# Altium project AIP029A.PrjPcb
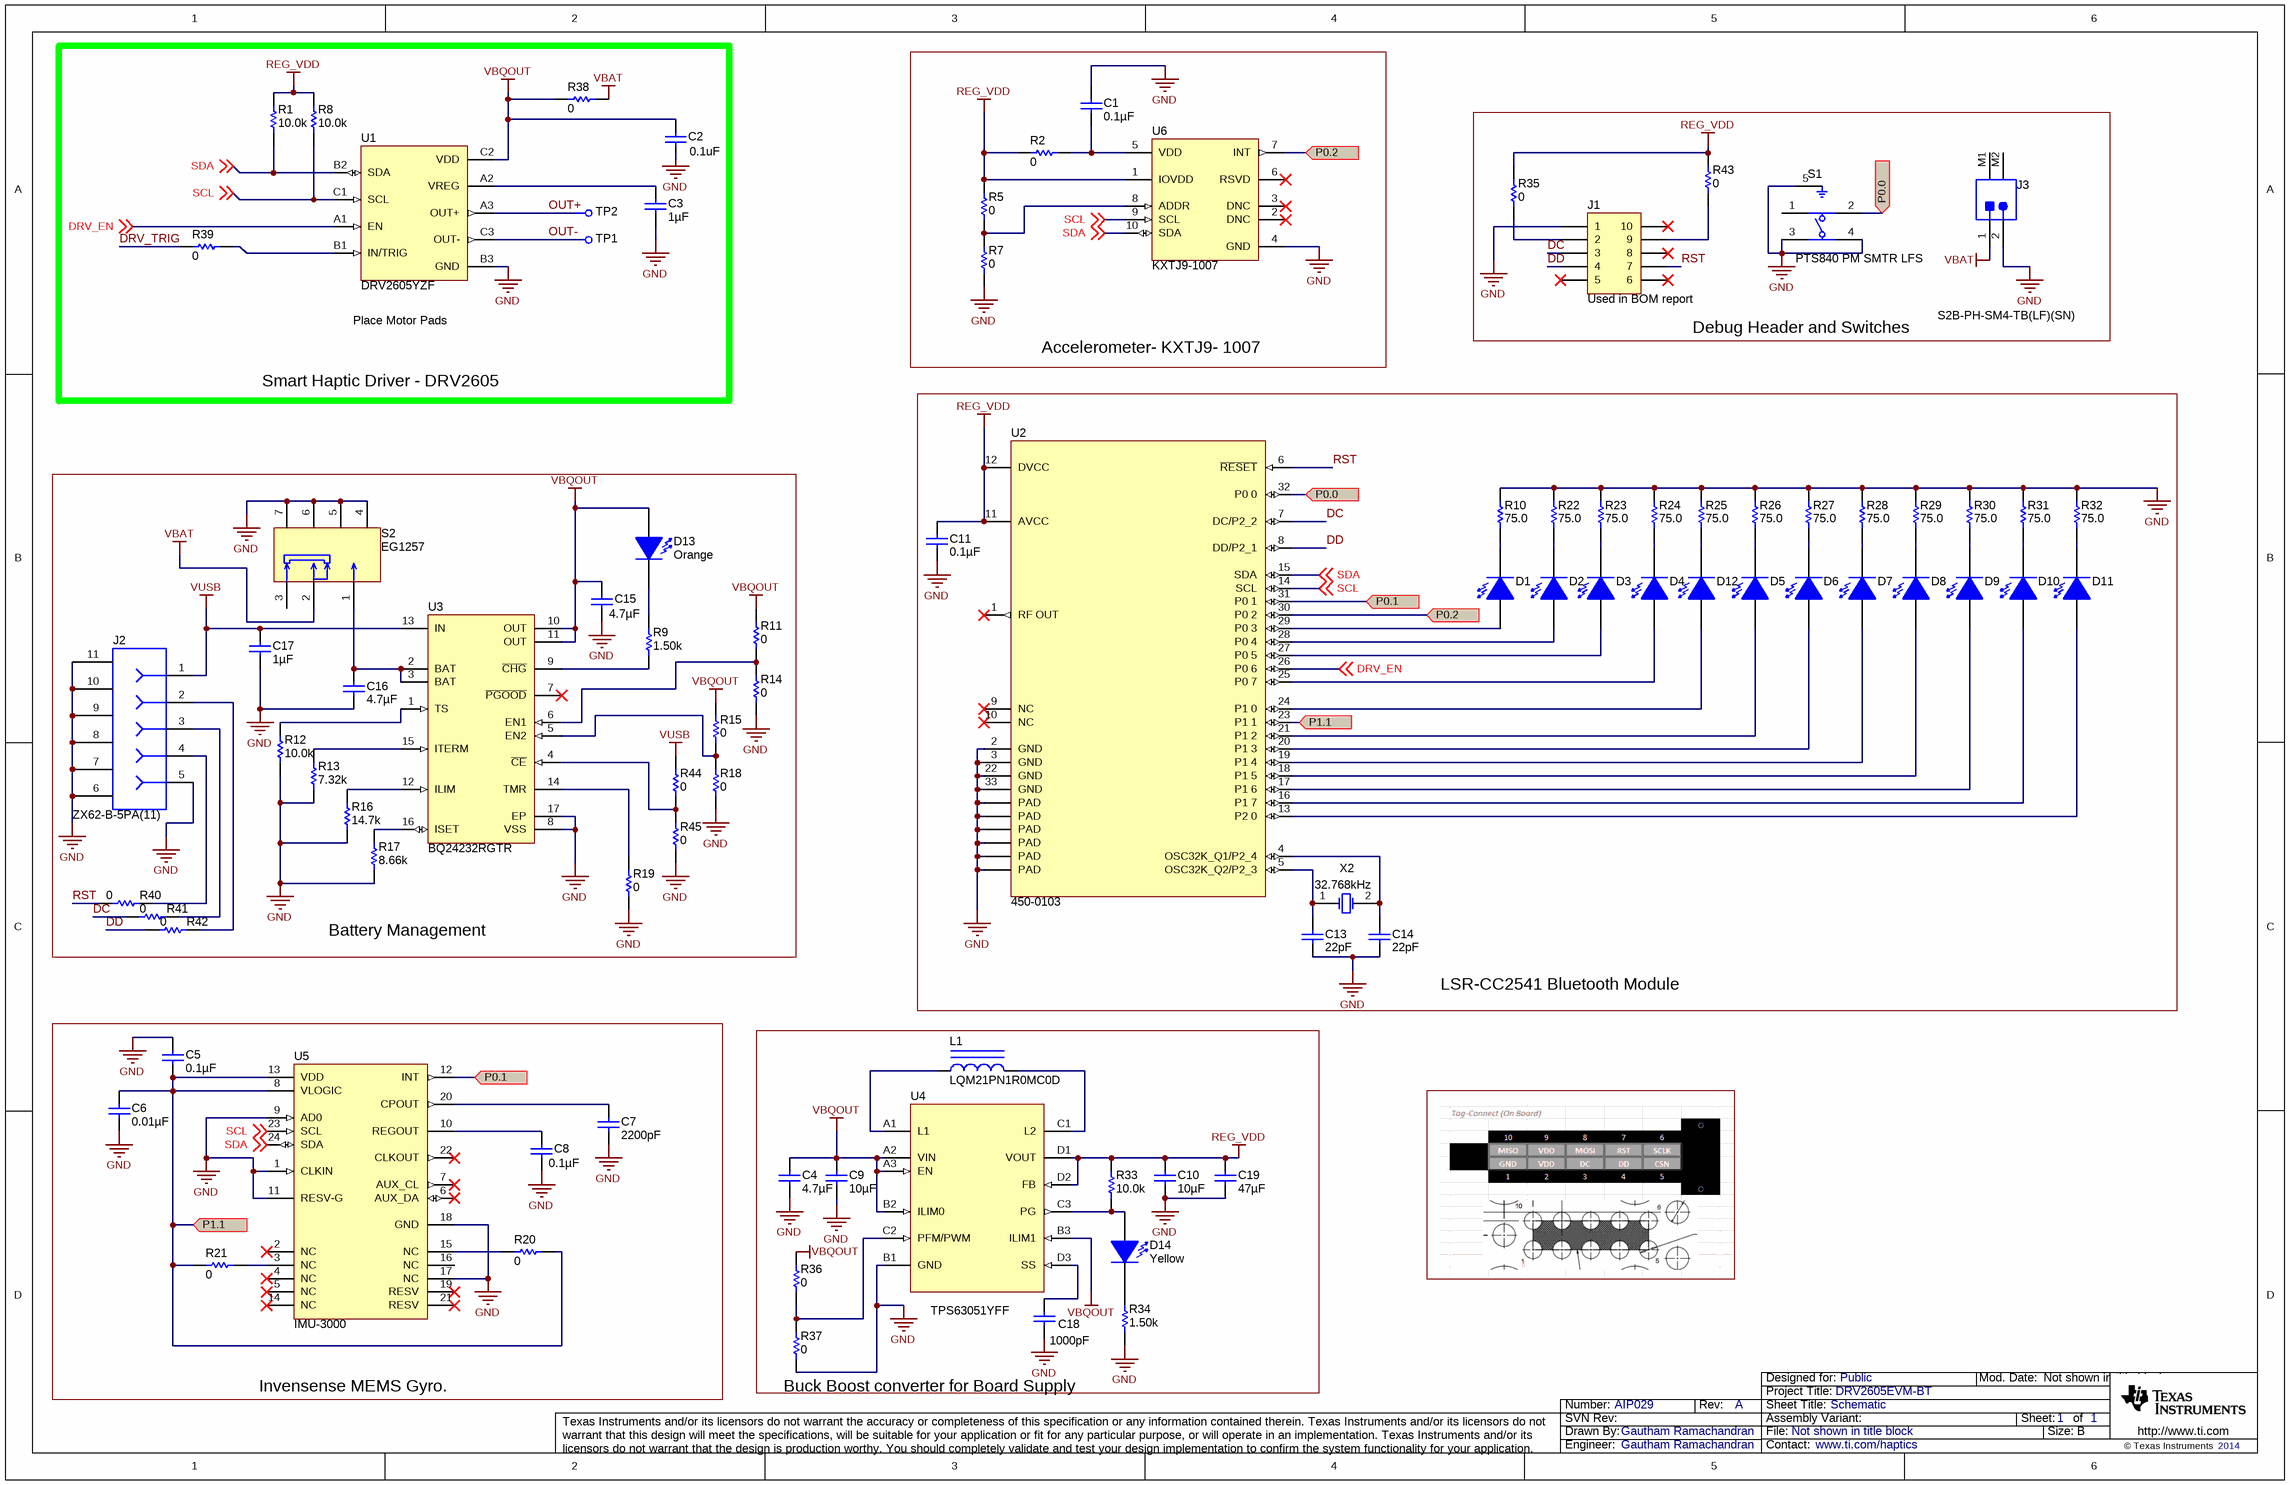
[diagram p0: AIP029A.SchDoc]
CopyrightYear: 2014; PCB_Layout: Gautham Ramachandran; PCB_Rev: A; PRJ_Customer: Public; PRJ_Engineer: Gautham Ramachandran; PRJ_Number: AIP029; PRJ_Title: DRV2605EVM-BT; SCH_Rev: A; TechSupport: www.ti.com/haptics
2 sheets, 96 parts. Net scope: flat (ports and power ports of the same name join across sheets).
Board file: AIP029A.PcbDoc
Sheets:
  AIP029A.SchDoc
  AIP029A_Hardware.SchDoc

## Sheet AIP029A.SchDoc: Schematic
size 431 x 279 mm; Date: Not shown in title block; ApprovedBy: Brian Burk; CheckedBy: Not shown in title block; Author: Gautham Ramachandran; CompanyName: Texas Instruments; DrawnBy: Gautham Ramachandran; Engineer: Brian Burk; Organization: Not shown in title block; Address1: Not shown in title block; Address2: Not shown in title block; Address3: Not shown in title block; DocumentNumber: 1; Revision: Use project parameter SCH_Rev; SheetNumber: 1; SheetTotal: 1; PageSetup: Record=PageOptions|CenterHorizontal=True|CenterVertical=True|PrintScale=0.62|XCorrection=1.00|YCorrection=1.00|PrintKind=0|BorderSize=5000000|LeftOffset=0|BottomOffset=0|Orientation=2|PaperLength=1000|PaperWidth=1000|Scale=100|PaperSource=15|PrintQuality=600|MediaType=1|DitherType=10|PaperKind=Letter|PrintScaleMode=1

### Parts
C1  ValueDisplayed: 0.1µF  [0402S]  (hidden comment: GRM155R71C104KA88D)
C2  value 0.1uF  [0402S]  (hidden comment: GRM155R71C104KA88D)
C3  ValueDisplayed: 1µF  [0402S]  (hidden comment: GRM155R61A105KE15D)
C4  ValueDisplayed: 4.7µF  [0402S]  (hidden comment: C1005X5R0J475M050BC)
C5  ValueDisplayed: 0.1µF  [0402S]  (hidden comment: GRM155R71A104KA01D)
C6  ValueDisplayed: 0.01µF  [0402S]  (hidden comment: GRM155R71E103KA01D)
C7  ValueDisplayed: 2200pF  [0402S]  (hidden comment: GRM155R71H222KA01D)
C8  ValueDisplayed: 0.1µF  [0402S]  (hidden comment: GRM155R71A104KA01D)
C9  ValueDisplayed: 10µF  [0603L]  (hidden comment: C1608X5R1A106M)
C10  ValueDisplayed: 10µF  [0603L]  (hidden comment: C1608X5R1A106M)
C11  ValueDisplayed: 0.1µF  [0402S]  (hidden comment: C1005X7R1H104K)
C13  ValueDisplayed: 22pF  [0402S]  (hidden comment: GRM1555C1H220JA01D)
C14  ValueDisplayed: 22pF  [0402S]  (hidden comment: GRM1555C1H220JA01D)
C15  ValueDisplayed: 4.7µF  [0402S]  (hidden comment: GRM155R61A475M)
C16  ValueDisplayed: 4.7µF  [0402S]  (hidden comment: GRM155R61A475M)
C17  ValueDisplayed: 1µF  [0402S]  (hidden comment: GRM155R61A105KE15D)
C18  ValueDisplayed: 1000pF  [0402S]  (hidden comment: C1005C0G1E102J)
C19  ValueDisplayed: 47µF  [0603]  (hidden comment: GRM188R60J476M)
D1  SML312WBCW1  [LED_SML]  (value not drawn)
D2  SML312WBCW1  [LED_SML]  (value not drawn)
D3  SML312WBCW1  [LED_SML]  (value not drawn)
D4  SML312WBCW1  [LED_SML]  (value not drawn)
D5  SML312WBCW1  [LED_SML]  (value not drawn)
D6  SML312WBCW1  [LED_SML]  (value not drawn)
D7  SML312WBCW1  [LED_SML]  (value not drawn)
D8  SML312WBCW1  [LED_SML]  (value not drawn)
D9  SML312WBCW1  [LED_SML]  (value not drawn)
D10  SML312WBCW1  [LED_SML]  (value not drawn)
D11  SML312WBCW1  [LED_SML]  (value not drawn)
D12  SML312WBCW1  [LED_SML]  (value not drawn)
D13  value Orange  [LED_SMLP12_ORANGE]  (hidden comment: SML-P12DTT86)
D14  value Yellow  [LED_SMLP12_Yellow]  (hidden comment: SML-P12YTT86)
J1  Used in BOM report  [PCBComponent_1]
J2  ZX62-B-5PA(11)  [CONN_USB_micro_ZX62-B-5PA]
J3  S2B-PH-SM4-TB(LF)(SN)  [JST_S2B-PH-SM4-TB]
L1  LQM21PN1R0MC0D  [0805]
R1  value 10.0k  [0402S]  (hidden comment: CRCW040210K0FKED)
R2  value 0  [0402S]  (hidden comment: CRCW04020000Z0ED)
R5  value 0  [0402S]  (hidden comment: CRCW04020000Z0ED)
R7  value 0  [0402S]  (hidden comment: CRCW04020000Z0ED)
R8  value 10.0k  [0402S]  (hidden comment: CRCW040210K0FKED)
R9  value 1.50k  [0402S]  (hidden comment: CRCW04021K50FKED)
R10  value 75.0  [0402S]  (hidden comment: CRCW040275R0FKED)
R11  value 0  [0402S]  (hidden comment: CRCW04020000Z0ED)
R12  value 10.0k  [0402S]  (hidden comment: CRCW040210K0FKED)
R13  value 7.32k  [0402S]  (hidden comment: CRCW04027K32FKED)
R14  value 0  [0402S]  (hidden comment: CRCW04020000Z0ED)
R15  value 0  [0402S]  (hidden comment: CRCW04020000Z0ED)
R16  value 14.7k  [0402S]  (hidden comment: CRCW040214K7FKED)
R17  value 8.66k  [0402S]  (hidden comment: CRCW04028K66FKED)
R18  value 0  [0402S]  (hidden comment: CRCW04020000Z0ED)
R19  value 0  [0402S]  (hidden comment: CRCW04020000Z0ED)
R20  value 0  [0402S]  (hidden comment: CRCW04020000Z0ED)
R21  value 0  [0402S]  (hidden comment: CRCW04020000Z0ED)
R22  value 75.0  [0402S]  (hidden comment: CRCW040275R0FKED)
R23  value 75.0  [0402S]  (hidden comment: CRCW040275R0FKED)
R24  value 75.0  [0402S]  (hidden comment: CRCW040275R0FKED)
R25  value 75.0  [0402S]  (hidden comment: CRCW040275R0FKED)
R26  value 75.0  [0402S]  (hidden comment: CRCW040275R0FKED)
R27  value 75.0  [0402S]  (hidden comment: CRCW040275R0FKED)
R28  value 75.0  [0402S]  (hidden comment: CRCW040275R0FKED)
R29  value 75.0  [0402S]  (hidden comment: CRCW040275R0FKED)
R30  value 75.0  [0402S]  (hidden comment: CRCW040275R0FKED)
R31  value 75.0  [0402S]  (hidden comment: CRCW040275R0FKED)
R32  value 75.0  [0402S]  (hidden comment: CRCW040275R0FKED)
R33  value 10.0k  [0402S]  (hidden comment: CRCW040210K0FKED)
R34  value 1.50k  [0402S]  (hidden comment: CRCW04021K50FKED)
R35  value 0  [0402S]  (hidden comment: CRCW04020000Z0ED)
R36  value 0  [0402S]  (hidden comment: CRCW04020000Z0ED)
R37  value 0  [0402S]  (hidden comment: CRCW04020000Z0ED)
R38  value 0  [0402S]  (hidden comment: CRCW04020000Z0ED)
R39  value 0  [0402S]  (hidden comment: CRCW04020000Z0ED)
R40  value 0  [0402S]  (hidden comment: CRCW04020000Z0ED)
R41  value 0  [0402S]  (hidden comment: CRCW04020000Z0ED)
R42  value 0  [0402S]  (hidden comment: CRCW04020000Z0ED)
R43  value 0  [0402S]  (hidden comment: CRCW04020000Z0ED)
R44  value 0  [0402L]  (hidden comment: CRCW04020000Z0ED)
R45  value 0  [0402S]  (hidden comment: CRCW04020000Z0ED)
S1  PTS840 PM SMTR LFS  [SW_PTS840 P]
S2  EG1257  [SW_EG1257]
TP1  (no value)  [DUMMY-PAD]
TP2  (no value)  [DUMMY-PAD]
U1  DRV2605YZF  [YZF0009ADAD]
U2  450-0103  [TiWi-uB1]
U3  BQ24232RGTR  [RGT0016C]
U4  TPS63051YFF  [YFF0012AFAF]
U5  IMU-3000  [QFN50P400X400X95-24N]
U6  KXTJ9-1007  [LGA3X3MM_0.65]
X2  Frequency: 32.768kHz  [XTAL_NX3215SA]  (hidden comment: NX3215SA-32.768K-STD-MUS-2)

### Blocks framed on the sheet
Smart Haptic Driver - DRV2605: C2 C3 R1 R8 R38 R39 TP1 TP2 U1
Accelerometer- KXTJ9- 1007: C1 R2 R5 R7 U6
Debug Header and Switches: J1 J3 R35 R43 S1
LSR-CC2541 Bluetooth Module: C11 C13 C14 D1-D12 R10 R22-R32 U2 X2
Battery Management: C15-C17 D13 J2 R9 R11-R19 R40-R42 R44 R45 S2 U3
Invensense MEMS Gyro.: C5-C8 R20 R21 U5
Buck Boost converter for Board Supply: C4 C9 C10 C18 C19 D14 L1 R33 R34 R36 R37 U4

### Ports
P0.0, P0.1, P0.2, P1.1

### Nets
GND: C1.1 C2.2 C3.2 C4.2 C5.1 C6.2 C7.2 C8.2 C9.2 C10.2 C11.1 C13.1 C14.1 C15.2 C16.2 C17.2 C18.2 C19.2 J1.1 J2.5 J2.6 J2.7 J2.8 J2.9 J2.10 J2.11 J3.2 R7.1 R10.1 R12.1 R13.1 R14.1 R16.1 R17.1 R18.1 R19.1 R22.1 R23.1 R24.1 R25.1 R26.1 R27.1 R28.1 R29.1 R30.1 R31.1 R32.1 R34.1 R37.1 R45.1 S1.3 S1.4 S1.5 S2.4 S2.5 S2.6 S2.7 U1.B3(GND) U2.2(GND) U2.3(GND) U2.22(GND) U2.33(GND) U2.34(PAD) U2.35(PAD) U2.36(PAD) U2.37(PAD) U2.38(PAD) U2.39(PAD) U3.8(VSS) U3.17(EP) U4.B1(GND) U5.1(CLKIN) U5.9(AD0) U5.11(RESV-G) U5.17(NC) U5.18(GND) U6.4(GND)
REG_VDD: C10.1 C11.2 C19.1 R1.2 R2.2 R5.2 R8.2 R33.2 R35.2 R43.2 U2.11(AVCC) U2.12(DVCC) U4.D1(VOUT) U4.D2(FB) U6.1(IOVDD)
VBAT: J3.1 R38.1 S2.2
VBQOUT: C2.1 C4.1 C9.1 C15.1 D13.1(A) R11.2 R15.2 R36.2 R38.2 U1.C2(VDD) U3.10(OUT) U3.11(OUT) U4.A2(VIN) U4.A3(EN) U4.B2(ILIM0) U4.B3(ILIM1)
VUSB: C17.1 J2.1 R44.2 U3.13(IN)
DC: J1.3 R41.2 U2.7(DC/P2_2)
DD: J1.4 R42.2 U2.8(DD/P2_1)
DRV_EN: U1.A1(EN) U2.26(P0_6) ; off-sheet DRV_EN
DRV_TRIG: R39.2
OUT+: U1.A3(OUT+)
OUT-: U1.C3(OUT-)
P0.0: S1.2 U2.32(P0_0) ; port P0.0
P0.1: U2.31(P0_1) U5.12(INT) ; port P0.1
P0.2: U2.30(P0_2) U6.7(INT) ; port P0.2
P1.1: C5.2 C6.1 R20.1 R21.2 U2.23(P1_1) U5.8(VLOGIC) U5.13(VDD) ; port P1.1
RST: J1.7 R40.2 U2.6(~{RESET})
SCL: R8.1 U1.C1(SCL) U2.14(SCL) U5.23(SCL) U6.9(SCL) ; off-sheet SCL
SDA: R1.1 U1.B2(SDA) U2.15(SDA) U5.24(SDA) U6.10(SDA) ; off-sheet SDA
NetC1_2: C1.2 R2.1 U6.5(VDD)
NetC3_1: C3.1 U1.A2(VREG)
NetC7_1: C7.1 U5.20(CPOUT)
NetC8_1: C8.1 U5.10(REGOUT)
NetC13_2: C13.2 U2.5(OSC32K_Q2/P2_3) X2.1(OSC1)
NetC14_2: C14.2 U2.4(OSC32K_Q1/P2_4) X2.2(OSC2)
NetC16_1: C16.1 S2.1 U3.2(BAT) U3.3(BAT)
NetC18_1: C18.1 U4.D3(SS)
NetD1_1: D1.1(A) U2.29(P0_3)
NetD1_2: D1.2(K) R10.2
NetD2_1: D2.1(A) U2.28(P0_4)
NetD2_2: D2.2(K) R22.2
NetD3_1: D3.1(A) U2.27(P0_5)
NetD3_2: D3.2(K) R23.2
NetD4_1: D4.1(A) U2.25(P0_7)
NetD4_2: D4.2(K) R24.2
NetD5_1: D5.1(A) U2.21(P1_2)
NetD5_2: D5.2(K) R26.2
NetD6_1: D6.1(A) U2.20(P1_3)
NetD6_2: D6.2(K) R27.2
NetD7_1: D7.1(A) U2.19(P1_4)
NetD7_2: D7.2(K) R28.2
NetD8_1: D8.1(A) U2.18(P1_5)
NetD8_2: D8.2(K) R29.2
NetD9_1: D9.1(A) U2.17(P1_6)
NetD9_2: D9.2(K) R30.2
NetD10_1: D10.1(A) U2.16(P1_7)
NetD10_2: D10.2(K) R31.2
NetD11_1: D11.1(A) U2.13(P2_0)
NetD11_2: D11.2(K) R32.2
NetD12_1: D12.1(A) U2.24(P1_0)
NetD12_2: D12.2(K) R25.2
NetD13_2: D13.2(K) R9.2
NetD14_1: D14.1(A) R33.1 U4.C3(PG)
NetD14_2: D14.2(K) R34.2
NetJ1_2: J1.2 R35.1
NetJ1_9: J1.9 R43.1
NetJ2_2: J2.2 R42.1
NetJ2_3: J2.3 R41.1
NetJ2_4: J2.4 R40.1
NetL1_1: L1.1 U4.A1(L1)
NetL1_2: L1.2 U4.C1(L2)
NetR5_1: R5.1 R7.2 U6.8(ADDR)
NetR9_1: R9.1 U3.9(~{CHG})
NetR11_1: R11.1 R14.2 U3.6(EN1)
NetR12_2: R12.2 U3.1(TS)
NetR13_2: R13.2 U3.15(ITERM)
NetR15_1: R15.1 R18.2 U3.5(EN2)
NetR16_2: R16.2 U3.12(ILIM)
NetR17_2: R17.2 U3.16(ISET)
NetR19_2: R19.2 U3.14(TMR)
NetR20_2: R20.2 U5.15(NC)
NetR21_1: R21.1 U5.3(NC)
NetR36_1: R36.1 R37.2 U4.C2(PFM/PWM)
NetR39_1: R39.1 U1.B1(IN/TRIG)
NetR44_1: R44.1 R45.2 U3.4(~{CE})

Not connected (* = marked no-connect by the designer): J1 5* 6* 8* 10*; J3 M1 M2; S1 1; S2 3; U2 1(RF_OUT)* 9(NC)* 10(NC)*; U3 7(~{PGOOD})*; U5 2(NC)* 4(NC)* 5(NC)* 6(AUX_DA)* 7(AUX_CL)* 14(NC)* 16(NC) 19(RESV)* 21(RESV)* 22(CLKOUT)*; U6 2(DNC)* 3(DNC)* 6(RSVD)*

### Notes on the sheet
- (near U1) Place Motor Pads

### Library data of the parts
C1 C2 = GRM155R71C104KA88D: CAP, CERM, 0.1uF, 16V, +/-10%, X7R, 0402; Manufacturer: MuRata; Polarized: N; CompType: Capacitor; U/M: EA; Cap_F: 0.0000001; Tolerance_%: 10; Value1: Unknown; VDC_V: 16; TaMin_C: -55; TaMax_C: 125; Cap_Case: 0402
C3 C17 = GRM155R61A105KE15D: CAP, CERM, 1uF, 10V, +/-10%, X5R, 0402; Manufacturer: MuRata; Polarized: N; CompType: Capacitor; U/M: EA; Cap_F: 0.000001; Tolerance_%: 10; Value1: Unknown; TaMin_C: -55; TaMax_C: 85; Cap_Case: 0402
C4 = C1005X5R0J475M050BC: CAP, CERM, 4.7uF, 6.3V, +/-20%, X5R, 0402; Manufacturer: TDK; Polarized: N; CompType: Capacitor; U/M: EA; Cap_F: 0.0000047; Tolerance_%: 20; Value1: Unknown; VDC_V: 6.3; TaMin_C: -55; TaMax_C: 85; Cap_Case: 0402
C5 C8 = GRM155R71A104KA01D: CAP, CERM, 0.1uF, 10V, +/-10%, X7R, 0402; Manufacturer: MuRata; Polarized: N; CompType: Capacitor; U/M: EA; Cap_F: 0.0000001; Tolerance_%: 10; Value1: Unknown; TaMin_C: -55; TaMax_C: 125; Cap_Case: 0402
C6 = GRM155R71E103KA01D: CAP, CERM, 0.01uF, 25V, +/-10%, X7R, 0402; Manufacturer: MuRata; Polarized: N; CompType: Capacitor; U/M: EA; Cap_F: 0.00000001; Tolerance_%: 10; Value1: Unknown; VDC_V: 25; TaMin_C: -55; TaMax_C: 125; Cap_Case: 0402
C7 = GRM155R71H222KA01D: CAP, CERM, 2200pF, 50V, +/-10%, X7R, 0402; Manufacturer: MuRata; Polarized: N; CompType: Capacitor; U/M: EA; Cap_F: 0.0000000022; Tolerance_%: 10; Value1: Unknown; VDC_V: 50; TaMin_C: -55; TaMax_C: 125; Cap_Case: 0402
C9 C10 = C1608X5R1A106M: CAP, CERM, 10uF, 10V, +/-20%, X5R, 0603; Manufacturer: TDK; Polarized: N; CompType: Capacitor; U/M: EA; Cap_F: 0.00001; Tolerance_%: 20; ESR_Ohm: 0.0078; Value1: 0.0078 ohm; VDC_V: 10; IRMS_A: 1.85; TaMin_C: -55; TaMax_C: 85; Cap_Case: 0603
C11 = C1005X7R1H104K: CAP, CERM, 0.1uF, 50V, +/-10%, C0G/NP0, 0402; Manufacturer: TDK; Polarized: N; CompType: Capacitor; U/M: EA; Cap_F: 0.0000001; Tolerance_%: 10; Value1: Unknown; VDC_V: 50; TaMin_C: -55; TaMax_C: 125; Cap_Case: 0402
C13 C14 = GRM1555C1H220JA01D: CAP, CERM, 22pF, 50V, +/-5%, C0G/NP0, 0402; Manufacturer: MuRata; Polarized: N; CompType: Capacitor; U/M: EA; Cap_F: 0.000000000022; Tolerance_%: 5; Value1: Unknown; VDC_V: 50; TaMin_C: -55; TaMax_C: 125; Cap_Case: 0402
C15 C16 = GRM155R61A475M: CAP, CERM, 4.7uF, 10V, +/-20%, X5R, 0402; Manufacturer: MuRata; Polarized: N; CompType: Capacitor; U/M: EA; Cap_F: 0.0000047; Tolerance_%: 20; Value1: Unknown; VDC_V: 10; TaMin_C: -55; TaMax_C: 85; Cap_Case: 0402
C18 = C1005C0G1E102J: CAP, CERM, 1000pF, 25V, +/-5%, C0G/NP0, 0402; Manufacturer: TDK; Polarized: N; CompType: Capacitor; U/M: EA; Cap_F: 0.000000001; Tolerance_%: 5; Value1: Unknown; VDC_V: 25; TaMin_C: -55; TaMax_C: 125; Cap_Case: 0402
C19 = GRM188R60J476M: CAP, CERM, 47uF, 6.3V, +/-20%, X5R, 0603; Manufacturer: MuRata; Polarized: N; CompType: Capacitor; U/M: EA; Cap_F: 0.000047; Tolerance_%: 20; Value1: Unknown; VDC_V: 6.3; TaMin_C: -55; TaMax_C: 85
D1-D12 = SML312WBCW1: LED, White, SMD; Manufacturer: Rohm; Type: AlInGaP; ColorTemperature: 8000K; Vf_V: 3; Value2: 3V; Io_A: 0.005; Value1: W; U/M: EA
D13 = SML-P12DTT86: LED, Orange, SMD; Manufacturer: Rohm; Type: InGaN; Vf_V: 2.1; Value2: 2.1V; Io_A: 0.02; Tjmax_C: 85; Value1: W; U/M: EA
D14 = SML-P12YTT86: LED, Yellow, SMD; Manufacturer: Rohm; Type: InGaN; Vf_V: 2.1; Value2: 2.1V; Io_A: 0.02; Tjmax_C: 85; Value1: W; U/M: EA
J1 = Component_1: SymbolVersion: use current date i.e. 2008-05-20; SymbolCreator: Use a-id; CompType: Used in some BOM reports.  Useful for finding later.; U/M: EA, IN, or GM
J2 = ZX62-B-5PA(11): Connector, micro USB Type B, Receptacle, R/A, SMD; Manufacturer: Hirose Electric Co. Ltd.; SymbolCreator: a0411947; U/M: EA
J3 = S2B-PH-SM4-TB(LF)(SN): Header, 2x1,2mm, R/A, SMT; Manufacturer: JST Manufacturing; SymbolCreator: x0208326; U/M: EA
L1 = LQM21PN1R0MC0D: Inductor, Multilayer, Ferrite, 1uH, 0.8A, 0.19 ohm, SMD; Manufacturer: MuRata; Ind_H: 1.0E-6; ValueDisplayed: 1µH; Imax_A: 0.8; Irms: 0.8A @ 40C rise; DCR_ohm: 0.19; U/M: EA
R1 R8 R12 R33 = CRCW040210K0FKED: RES, 10.0k ohm, 1%, 0.063W, 0402; Manufacturer: Vishay-Dale; CompType: Resistor; Res_ohm: 10000; Value_Code: 10k0; Tolerance_%: 1; Power_W: 0.063; VDC_V: 50; TempCo: 100 ppm/C; EIA_Code: E96; U/M: EA
R2 R5 R7 R11 R14 R15 R18-R21 R35-R45 = CRCW04020000Z0ED: RES, 0 ohm, 5%, 0.063W, 0402; Manufacturer: Vishay-Dale; CompType: Resistor; Value_Code: 0000; Tolerance_%: 5; Power_W: 0.063; VDC_V: 50; TempCo: 200 ppm/C; EIA_Code: E24; U/M: EA
R9 R34 = CRCW04021K50FKED: RES, 1.50k ohm, 1%, 0.063W, 0402; Manufacturer: Vishay-Dale; CompType: Resistor; Res_ohm: 1500; Value_Code: 1k50; Tolerance_%: 1; Power_W: 0.063; VDC_V: 50; TempCo: 100 ppm/C; EIA_Code: E96; U/M: EA
R10 R22-R32 = CRCW040275R0FKED: RES, 75.0 ohm, 1%, 0.063W, 0402; Manufacturer: Vishay-Dale; CompType: Resistor; Res_ohm: 75; Value_Code: 75R0; Tolerance_%: 1; Power_W: 0.063; VDC_V: 50; TempCo: 100 ppm/C; EIA_Code: E96; U/M: EA
R13 = CRCW04027K32FKED: RES, 7.32k ohm, 1%, 0.063W, 0402; Manufacturer: Vishay-Dale; CompType: Resistor; Res_ohm: 7320; Value_Code: 7k32; Tolerance_%: 1; Power_W: 0.063; VDC_V: 50; TempCo: 100 ppm/C; EIA_Code: E96; U/M: EA
R16 = CRCW040214K7FKED: RES, 14.7k ohm, 1%, 0.063W, 0402; Manufacturer: Vishay-Dale; CompType: Resistor; Res_ohm: 14700; Value_Code: 14k7; Tolerance_%: 1; Power_W: 0.063; VDC_V: 50; TempCo: 100 ppm/C; EIA_Code: E96; U/M: EA
R17 = CRCW04028K66FKED: RES, 8.66k ohm, 1%, 0.063W, 0402; Manufacturer: Vishay-Dale; CompType: Resistor; Res_ohm: 8660; Value_Code: 8k66; Tolerance_%: 1; Power_W: 0.063; VDC_V: 50; TempCo: 100 ppm/C; EIA_Code: E96; U/M: EA
S1 = PTS840 PM SMTR LFS: SWITCH TACTILE SPST-NO 0.05A 12V, SMT; Manufacturer: C&K Components; SymbolCreator: x0208325; VDC_V: 12; SwitchFunction: Off-Mom; PositionCount: 1; CurrentRating_mA: 50
S2 = EG1257: Switch, Slide, SPDT, 0.3A, SMT; Manufacturer: E-Switch; SymbolCreator: a0411947; VDC_V: 4; SwitchFunction: On-On; PositionCount: 2; CurrentRating_mA: 300
TP1 TP2 = DUMMY-PIN: PAD, 5X5mm; Manufacturer: STD; area: 390; Value: STD
U1 = DRV2605YZF: Haptic Driver for ERM and LRA with Built-In Library and Smart Loop Architecture, YZF0009ADAD; Alternate Manufacturer: None; Manufacturer: Texas Instruments; SymbolCreator: a0411947; CompType: IC; U/M: EA
U2 = TiWi-uB1: BLUETOOTH SMART (BLE) MODULE; Manufacturer: LS RESEARCH; SymbolCreator: a0411947
U3 = BQ24232RGTR: USB Friendly 0.5 A Li+ Charger with Dynamic Power Management, 10.5 V OVP, 4.3 V, -40 to 85 degC, 16-pin QFN (RGT), Green (RoHS & no Sb/Br); Manufacturer: Texas Instruments; Alternate Manufacturer: None; Alternate PartNumber: Equivalent; Lead Acid: N; SubFamily: Battery Charge Management; Vin(Min)(V): 4.3
U4 = TPS63051YFF: SINGLE INDUCTOR BUCK-BOOST WITH 1A SWITCHES AND ADJUSTABLE SOFT START, YFF0012AFAF; Alternate Manufacturer: None; Manufacturer: Texas Instruments; SymbolCreator: a0799628; CompType: IC; U/M: EA
U5 = IMU-3000: Motion Processing Unit, QFN-24; Manufacturer: InvenSense; SymbolCreator: a0411947
U6 = KXTJ9-1007: ± 2g / 4g / 8g Tri-axis Digital Accelerometer, SMT; Manufacturer: Kionix; SymbolCreator: a0799628
X2 = NX3215SA-32.768K-STD-MUS-2: Crystal, 32.768kHz, 12.5pF, SMD; Manufacturer: NDK; SymbolCreator: a0412235; U/M: EA; TaMin_C: -40; TaMax_C: 125; Frequency Stability: ±20ppm

## Sheet AIP029A_Hardware.SchDoc: Hardware
size 431 x 279 mm; Date: Not shown in title block; ApprovedBy: Not shown in title block; CheckedBy: Not shown in title block; Author: Not shown in title block; CompanyName: Not shown in title block; DrawnBy: Gautham Ramachandran; Engineer: Gautham Ramachandran; Organization: Not shown in title block; Address1: Not shown in title block; Address2: Not shown in title block; Address3: Not shown in title block; Address4: Not shown in title block; DocumentNumber: 1; Revision: Use project parameter SCH_Rev; SheetNumber: 1; SheetTotal: 1; PageSetup: Record=PageOptions|CenterHorizontal=True|CenterVertical=True|PrintScale=1.00|XCorrection=1.00|YCorrection=1.00|PrintKind=0|BorderSize=5000000|LeftOffset=0|BottomOffset=0|Orientation=2|PaperLength=1000|PaperWidth=1000|Scale=100|PaperSource=15|PrintQuality=600|MediaType=1|DitherType=10|PaperKind=Letter|PrintScaleMode=1
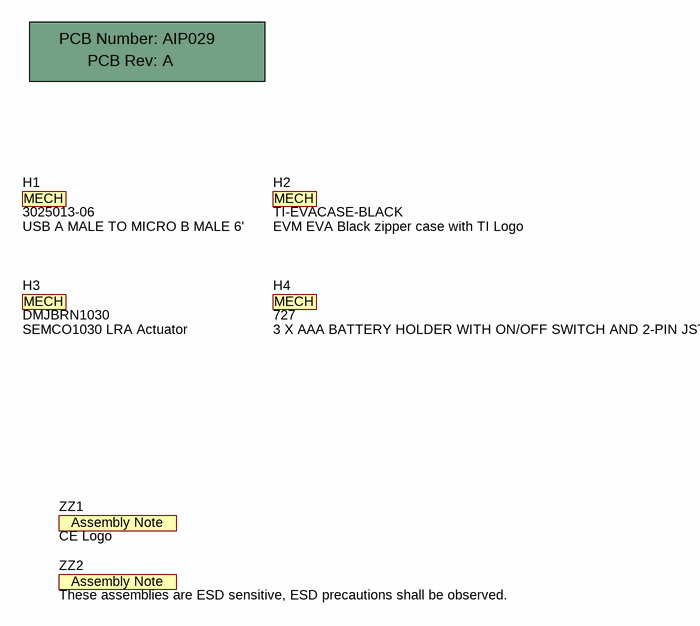
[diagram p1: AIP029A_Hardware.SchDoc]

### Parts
!PCB  Printed Circuit Board  (value not drawn)  (mechanical)
H1  3025013-06  (mechanical)
H2  TI-EVACASE-BLACK  (mechanical)
H3  DMJBRN1030  (mechanical)
H4  727  (mechanical)
ZZ1  CE Logo  [AssemblyNote]  (no BOM)
ZZ2  These assemblies are ESD sensitive, ESD precautions shall be observed.  [AssemblyNote]  (no BOM)

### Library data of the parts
!PCB = PCB: Manufacturer: Any; PartNumber: AIP029; SymbolCreator: a0412235
H1 = MechPart: USB A MALE TO MICRO B MALE 6'; Manufacturer: Qualtek; SymbolCreator: codlsc; CompType: USB Micro Cable; U/M: EA
H2 = MechPart: EVM EVA Black zipper case with TI Logo; Manufacturer: Royal Case; SymbolCreator: codlsc; CompType: EVM Case; U/M: EA
H3 = MechPart: SEMCO1030 LRA Actuator; Manufacturer: Samsung Electro-Mechanics; SymbolCreator: codlsc; CompType: Vibration Motor; U/M: EA
H4 = MechPart: 3 X AAA BATTERY HOLDER WITH ON/OFF SWITCH AND 2-PIN JST; Manufacturer: Adafruit; SymbolCreator: codlsc; CompType: AAA Battery Pack; U/M: EA
ZZ1 ZZ2 = AssemblyNote: SymbolCreator: codlsc

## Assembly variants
Internal Release: not fitted J1 R5 R14 R15 R36 R38 R40 R41 R42 R43 R45 TP1 TP2 ZZ2
001: not fitted J1 R5 R14 R15 R36 R38 R40 R41 R42 R43 R45 TP1 TP2 U5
